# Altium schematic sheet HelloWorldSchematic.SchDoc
size A
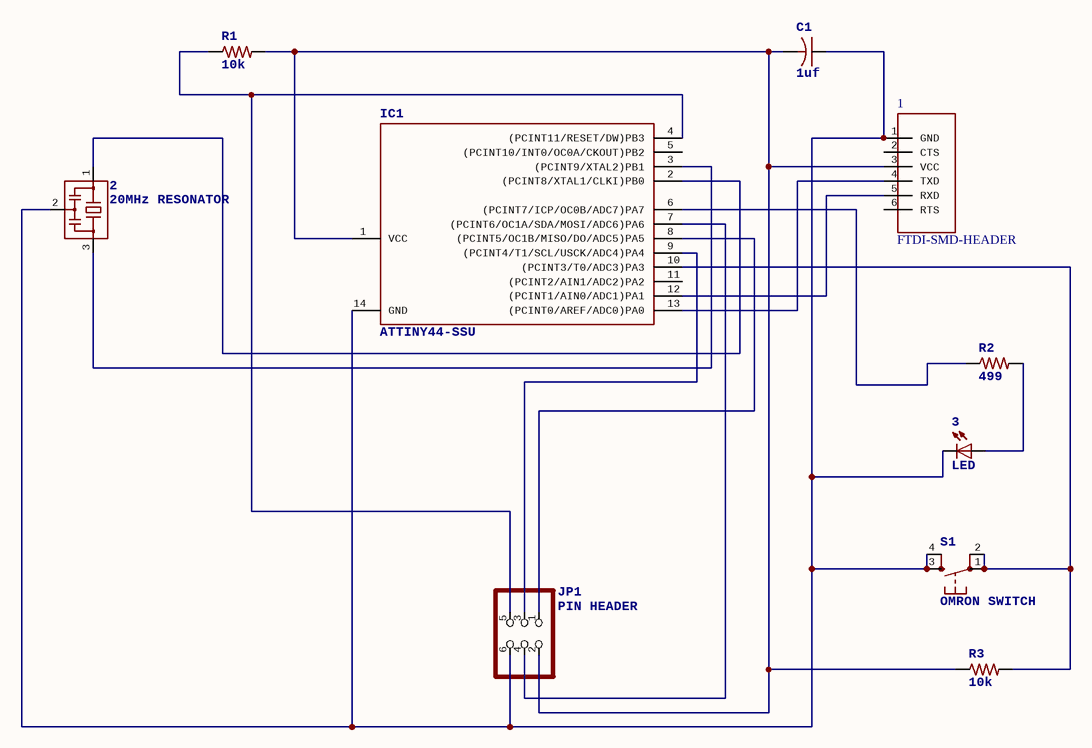
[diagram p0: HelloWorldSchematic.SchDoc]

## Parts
1  FTDI-SMD-HEADER  [1X06SMD]
2  20MHz RESONATOR  [EFOBM]
3  LED  [LED1206FAB]
C1  1uf  [C1206]
IC1  ATTINY44-SSU  [SOIC14]
JP1  PIN HEADER  [2X03SMD]
R1  10k  [R1206]
R2  499  [R1206]
R3  10k  [R1206]
S1  OMRON SWITCH  [6MM_SWITCH]

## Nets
Net1_1: 1.1(GND) 2.2 3.2(C) C1.1 IC1.14(GND) JP1.6 S1.3(S) S1.4(S1)
Net1_3: 1.3(VCC) C1.2 IC1.1(VCC) JP1.2 R1.2 R3.1
Net1_4: 1.4(TXD) IC1.13((PCINT0/AREF/ADC0)PA0)
Net1_5: 1.5(RXD) IC1.12((PCINT1/AIN0/ADC1)PA1)
Net2_1: 2.1 IC1.2((PCINT8/XTAL1/CLKI)PB0)
Net2_3: 2.3 IC1.3((PCINT9/XTAL2)PB1)
Net3_1: 3.1(A) R2.2
NetIC1_4: IC1.4((PCINT11/RESET/DW)PB3) JP1.5 R1.1
NetIC1_6: IC1.6((PCINT7/ICP/OC0B/ADC7)PA7) R2.1
NetIC1_7: IC1.7((PCINT6/OC1A/SDA/MOSI/ADC6)PA6) JP1.4
NetIC1_8: IC1.8((PCINT5/OC1B/MISO/DO/ADC5)PA5) JP1.1
NetIC1_9: IC1.9((PCINT4/T1/SCL/USCK/ADC4)PA4) JP1.3
NetIC1_10: IC1.10((PCINT3/T0/ADC3)PA3) R3.2 S1.1(P) S1.2(P1)

Not connected (* = marked no-connect by the designer): 1 2(CTS) 6(RTS); IC1 5((PCINT10/INT0/OC0A/CKOUT)PB2) 11((PCINT2/AIN1/ADC2)PA2)

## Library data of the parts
2 = RESONATOR
3 = LEDFAB1206
C1 = CAP-US1206
JP1 = PINHD-2X3-SMD
R1-R3 = RES-US1206
S1 = 6MM_SWITCH6MM_SWITCH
